Omron CX-Programmer project 新規ﾌﾟﾛｼﾞｪｸﾄ (CX-Programmer 9.73)

# PLC 受電PLC: CJ2M CPU34
I/O table (CPU CJ2M-CPU34): rack 0 slot 0 CJ1W-ID231; rack 0 slot 1 CJ1W-OD231; rack 0 slot 2 CJ1W-AD081; rack 0 slot 11 CJ2M-EIP21

## Global symbols (name address type ; comment)
0.00 BOOL  ; 自動運転
0.01 BOOL  ; ﾏｽﾀｰｽｲｯﾁ切
0.02 BOOL  ; ﾏｽﾀｰｽｲｯﾁ入
0.03 BOOL  ; CB0選択
0.04 BOOL  ; CB1選択
0.05 BOOL  ; CB2選択
0.06 BOOL  ; CB3選択
0.07 BOOL  ; CB4選択
0.08 BOOL  ; CB5選択
0.09 BOOL  ; CB6選択
0.10 BOOL  ; CB7選択
0.11 BOOL  ; CB8選択
2000 CHANNEL  ; ﾋﾟｰｸﾎｰﾙﾄﾞ機能
2001 CHANNEL  ; 受電電力
2002 CHANNEL  ; 1号機発電電力
2003 CHANNEL  ; 2号機発電電力
2004 CHANNEL  ; 負荷1電力
2005 CHANNEL  ; 負荷2電力
2006 CHANNEL  ; 負荷3電力
2009 CHANNEL  ; ｱﾗｰﾑﾌﾗｸﾞ/断線検知
2.00 BOOL  ; CB0(受電) ON
2.01 BOOL  ; CB1（G1） ON
2.02 BOOL  ; CB2(G2) ON
2.03 BOOL  ; CB3(L1) ON
2.04 BOOL  ; CB4(L2) ON
2.05 BOOL  ; CB5(L3) ON
2.06 BOOL  ; CB6(L1)ON
2.07 BOOL  ; CB7(L3)ON
2.08 BOOL  ; CB8(L3)ON
3.00 BOOL  ; CB0(受電)選択
3.01 BOOL  ; CB1(G1)選択
3.02 BOOL  ; CB2(G2)選択
3.03 BOOL  ; CB3(L1)選択
3.04 BOOL  ; CB4(L2)選択
3.05 BOOL  ; CB5(L3)選択
3.06 BOOL  ; CB6(L1)選択
3.07 BOOL  ; CB7(L3)選択
3.08 BOOL  ; CB8(L3)選択
D0 CHANNEL  ; 受電電力kW
D1 CHANNEL  ; 発電機G1出力kW
D2 CHANNEL  ; 発電機G2出力kW
D3 CHANNEL  ; 負荷L1電力kW
D4 CHANNEL  ; 負荷L2電力kW
D5 CHANNEL  ; 負荷L3電力kW
T0000 BOOL  ; CB1(G1)ON遅延
T0001 BOOL  ; CB2(G2)ON遅延
T0002 BOOL  ; CB1(G1)OFF
T0003 BOOL  ; CB2(G2)OFF遅延
W0.01 BOOL  ; CB1選択
W0.02 BOOL  ; CB2選択
W5.00 BOOL  ; 発電機運転0台
W5.01 BOOL  ; 発電機運転1台
W5.02 BOOL  ; 発電機運転2台
W5.03 BOOL  ; CB1(G1)OFF
W5.04 BOOL  ; CB2(G2)OFF

## Program 制御ﾌﾟﾛｸﾞﾗﾑ (cyclic task 0)

### Section 自動

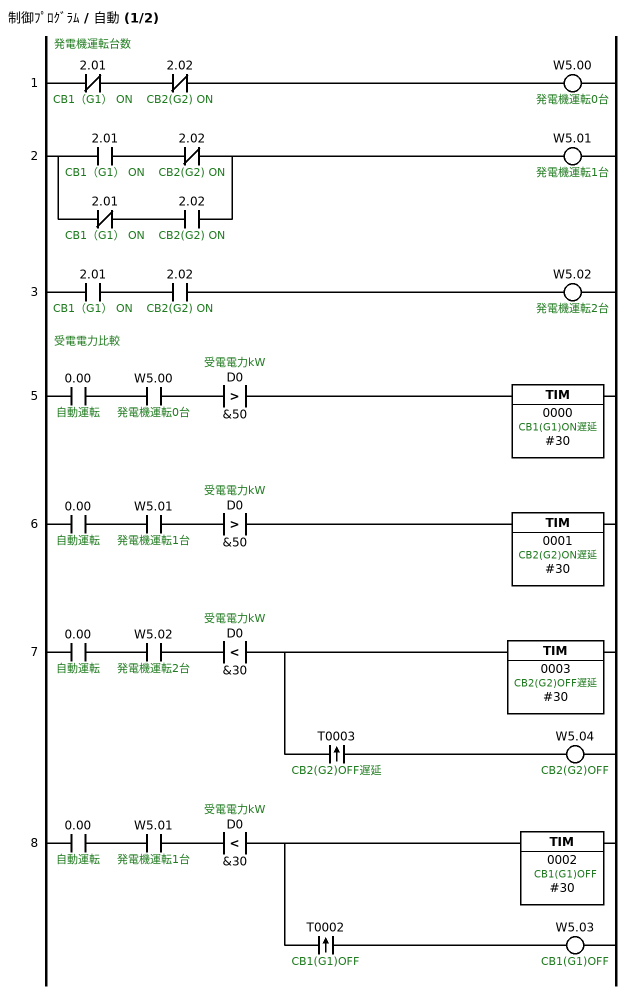
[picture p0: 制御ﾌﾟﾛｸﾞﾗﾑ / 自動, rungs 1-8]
; rung 1: 発電機運転台数
LDNOT 2.01  ; CB1（G1） ON
ANDNOT 2.02  ; CB2(G2) ON
OUT W5.00  ; 発電機運転0台
; rung 2
LD 2.01  ; CB1（G1） ON
ANDNOT 2.02  ; CB2(G2) ON
LDNOT 2.01  ; CB1（G1） ON
AND 2.02  ; CB2(G2) ON
ORLD
OUT W5.01  ; 発電機運転1台
; rung 3
LD 2.01  ; CB1（G1） ON
AND 2.02  ; CB2(G2) ON
OUT W5.02  ; 発電機運転2台
; rung 5: 受電電力比較
LD 0.00  ; 自動運転
AND W5.00  ; 発電機運転0台
AND>(320) D0 &50  ; 受電電力kW
TIM 0000 #30  ; CB1(G1)ON遅延
; rung 6
LD 0.00  ; 自動運転
AND W5.01  ; 発電機運転1台
AND>(320) D0 &50  ; 受電電力kW
TIM 0001 #30  ; CB2(G2)ON遅延
; rung 7
LD 0.00  ; 自動運転
AND W5.02  ; 発電機運転2台
AND<(310) D0 &30  ; 受電電力kW
TIM 0003 #30  ; CB2(G2)OFF遅延
@AND T0003  ; CB2(G2)OFF遅延
OUT W5.04  ; CB2(G2)OFF
; rung 8
LD 0.00  ; 自動運転
AND W5.01  ; 発電機運転1台
AND<(310) D0 &30  ; 受電電力kW
TIM 0002 #30  ; CB1(G1)OFF
@AND T0002  ; CB1(G1)OFF
OUT W5.03  ; CB1(G1)OFF

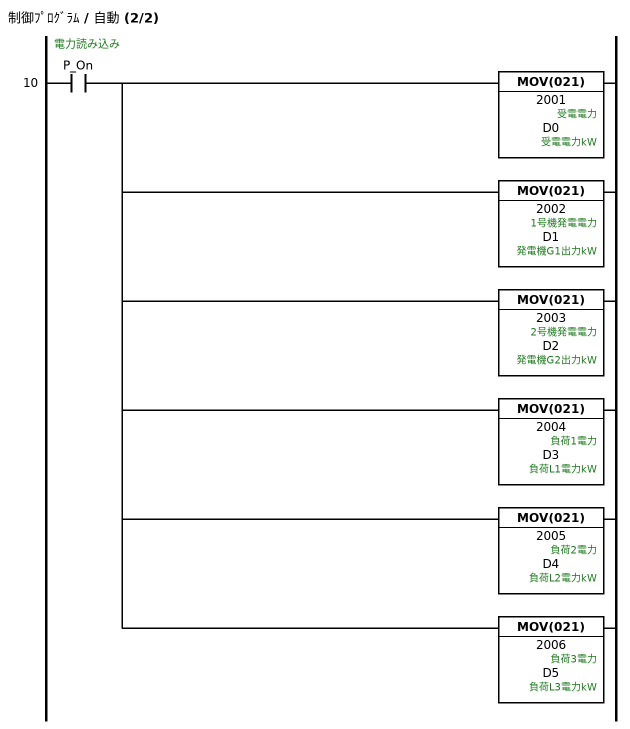
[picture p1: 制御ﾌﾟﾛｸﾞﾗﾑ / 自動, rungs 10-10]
; rung 10: 電力読み込み
LD P_On
MOV(021) 2001 D0  ; 受電電力, 受電電力kW
MOV(021) 2002 D1  ; 1号機発電電力, 発電機G1出力kW
MOV(021) 2003 D2  ; 2号機発電電力, 発電機G2出力kW
MOV(021) 2004 D3  ; 負荷1電力, 負荷L1電力kW
MOV(021) 2005 D4  ; 負荷2電力, 負荷L2電力kW
MOV(021) 2006 D5  ; 負荷3電力, 負荷L3電力kW

### Section 手動

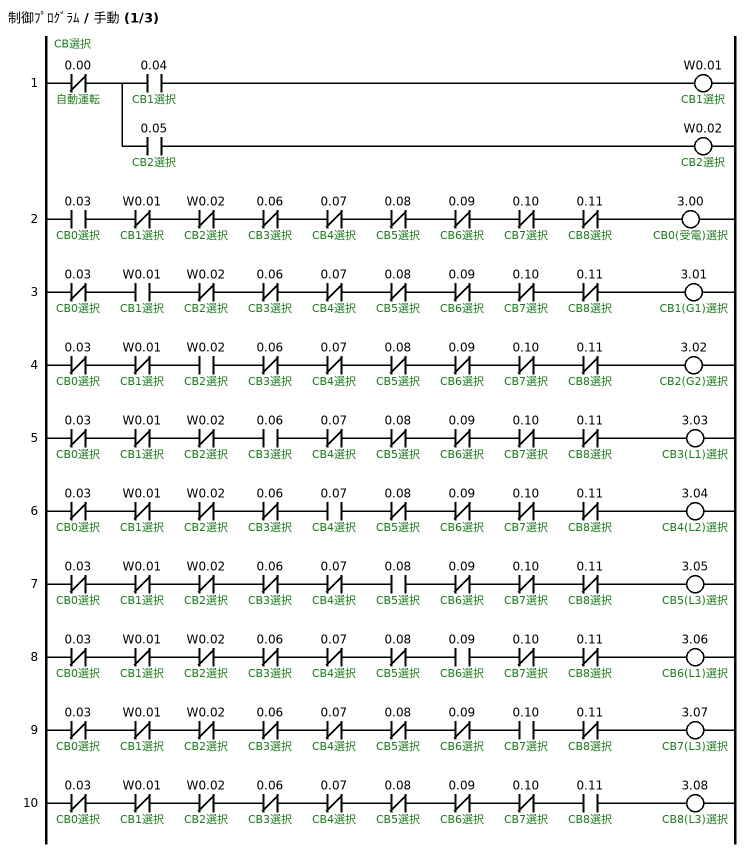
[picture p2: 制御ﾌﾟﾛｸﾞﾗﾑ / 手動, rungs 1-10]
; rung 1: CB選択
LDNOT 0.00  ; 自動運転
OUT TR0
AND 0.04  ; CB1選択
OUT W0.01  ; CB1選択
LD TR0
AND 0.05  ; CB2選択
OUT W0.02  ; CB2選択
; rung 2
LD 0.03  ; CB0選択
ANDNOT W0.01  ; CB1選択
ANDNOT W0.02  ; CB2選択
ANDNOT 0.06  ; CB3選択
ANDNOT 0.07  ; CB4選択
ANDNOT 0.08  ; CB5選択
ANDNOT 0.09  ; CB6選択
ANDNOT 0.10  ; CB7選択
ANDNOT 0.11  ; CB8選択
OUT 3.00  ; CB0(受電)選択
; rung 3
LDNOT 0.03  ; CB0選択
AND W0.01  ; CB1選択
ANDNOT W0.02  ; CB2選択
ANDNOT 0.06  ; CB3選択
ANDNOT 0.07  ; CB4選択
ANDNOT 0.08  ; CB5選択
ANDNOT 0.09  ; CB6選択
ANDNOT 0.10  ; CB7選択
ANDNOT 0.11  ; CB8選択
OUT 3.01  ; CB1(G1)選択
; rung 4
LDNOT 0.03  ; CB0選択
ANDNOT W0.01  ; CB1選択
AND W0.02  ; CB2選択
ANDNOT 0.06  ; CB3選択
ANDNOT 0.07  ; CB4選択
ANDNOT 0.08  ; CB5選択
ANDNOT 0.09  ; CB6選択
ANDNOT 0.10  ; CB7選択
ANDNOT 0.11  ; CB8選択
OUT 3.02  ; CB2(G2)選択
; rung 5
LDNOT 0.03  ; CB0選択
ANDNOT W0.01  ; CB1選択
ANDNOT W0.02  ; CB2選択
AND 0.06  ; CB3選択
ANDNOT 0.07  ; CB4選択
ANDNOT 0.08  ; CB5選択
ANDNOT 0.09  ; CB6選択
ANDNOT 0.10  ; CB7選択
ANDNOT 0.11  ; CB8選択
OUT 3.03  ; CB3(L1)選択
; rung 6
LDNOT 0.03  ; CB0選択
ANDNOT W0.01  ; CB1選択
ANDNOT W0.02  ; CB2選択
ANDNOT 0.06  ; CB3選択
AND 0.07  ; CB4選択
ANDNOT 0.08  ; CB5選択
ANDNOT 0.09  ; CB6選択
ANDNOT 0.10  ; CB7選択
ANDNOT 0.11  ; CB8選択
OUT 3.04  ; CB4(L2)選択
; rung 7
LDNOT 0.03  ; CB0選択
ANDNOT W0.01  ; CB1選択
ANDNOT W0.02  ; CB2選択
ANDNOT 0.06  ; CB3選択
ANDNOT 0.07  ; CB4選択
AND 0.08  ; CB5選択
ANDNOT 0.09  ; CB6選択
ANDNOT 0.10  ; CB7選択
ANDNOT 0.11  ; CB8選択
OUT 3.05  ; CB5(L3)選択
; rung 8
LDNOT 0.03  ; CB0選択
ANDNOT W0.01  ; CB1選択
ANDNOT W0.02  ; CB2選択
ANDNOT 0.06  ; CB3選択
ANDNOT 0.07  ; CB4選択
ANDNOT 0.08  ; CB5選択
AND 0.09  ; CB6選択
ANDNOT 0.10  ; CB7選択
ANDNOT 0.11  ; CB8選択
OUT 3.06  ; CB6(L1)選択
; rung 9
LDNOT 0.03  ; CB0選択
ANDNOT W0.01  ; CB1選択
ANDNOT W0.02  ; CB2選択
ANDNOT 0.06  ; CB3選択
ANDNOT 0.07  ; CB4選択
ANDNOT 0.08  ; CB5選択
ANDNOT 0.09  ; CB6選択
AND 0.10  ; CB7選択
ANDNOT 0.11  ; CB8選択
OUT 3.07  ; CB7(L3)選択
; rung 10
LDNOT 0.03  ; CB0選択
ANDNOT W0.01  ; CB1選択
ANDNOT W0.02  ; CB2選択
ANDNOT 0.06  ; CB3選択
ANDNOT 0.07  ; CB4選択
ANDNOT 0.08  ; CB5選択
ANDNOT 0.09  ; CB6選択
ANDNOT 0.10  ; CB7選択
AND 0.11  ; CB8選択
OUT 3.08  ; CB8(L3)選択

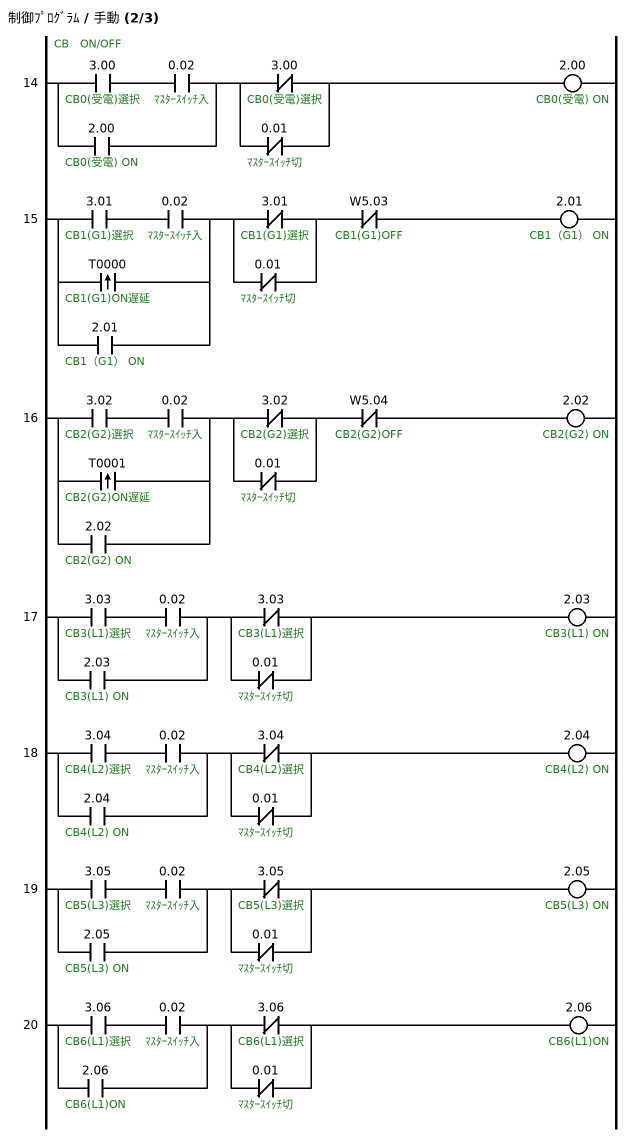
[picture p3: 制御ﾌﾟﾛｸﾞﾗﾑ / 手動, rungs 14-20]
; rung 14: CB　ON/OFF
LD 3.00  ; CB0(受電)選択
AND 0.02  ; ﾏｽﾀｰｽｲｯﾁ入
OR 2.00  ; CB0(受電) ON
LDNOT 3.00  ; CB0(受電)選択
ORNOT 0.01  ; ﾏｽﾀｰｽｲｯﾁ切
ANDLD
OUT 2.00  ; CB0(受電) ON
; rung 15
LD 3.01  ; CB1(G1)選択
AND 0.02  ; ﾏｽﾀｰｽｲｯﾁ入
@OR T0000  ; CB1(G1)ON遅延
OR 2.01  ; CB1（G1） ON
LDNOT 3.01  ; CB1(G1)選択
ORNOT 0.01  ; ﾏｽﾀｰｽｲｯﾁ切
ANDLD
ANDNOT W5.03  ; CB1(G1)OFF
OUT 2.01  ; CB1（G1） ON
; rung 16
LD 3.02  ; CB2(G2)選択
AND 0.02  ; ﾏｽﾀｰｽｲｯﾁ入
@OR T0001  ; CB2(G2)ON遅延
OR 2.02  ; CB2(G2) ON
LDNOT 3.02  ; CB2(G2)選択
ORNOT 0.01  ; ﾏｽﾀｰｽｲｯﾁ切
ANDLD
ANDNOT W5.04  ; CB2(G2)OFF
OUT 2.02  ; CB2(G2) ON
; rung 17
LD 3.03  ; CB3(L1)選択
AND 0.02  ; ﾏｽﾀｰｽｲｯﾁ入
OR 2.03  ; CB3(L1) ON
LDNOT 3.03  ; CB3(L1)選択
ORNOT 0.01  ; ﾏｽﾀｰｽｲｯﾁ切
ANDLD
OUT 2.03  ; CB3(L1) ON
; rung 18
LD 3.04  ; CB4(L2)選択
AND 0.02  ; ﾏｽﾀｰｽｲｯﾁ入
OR 2.04  ; CB4(L2) ON
LDNOT 3.04  ; CB4(L2)選択
ORNOT 0.01  ; ﾏｽﾀｰｽｲｯﾁ切
ANDLD
OUT 2.04  ; CB4(L2) ON
; rung 19
LD 3.05  ; CB5(L3)選択
AND 0.02  ; ﾏｽﾀｰｽｲｯﾁ入
OR 2.05  ; CB5(L3) ON
LDNOT 3.05  ; CB5(L3)選択
ORNOT 0.01  ; ﾏｽﾀｰｽｲｯﾁ切
ANDLD
OUT 2.05  ; CB5(L3) ON
; rung 20
LD 3.06  ; CB6(L1)選択
AND 0.02  ; ﾏｽﾀｰｽｲｯﾁ入
OR 2.06  ; CB6(L1)ON
LDNOT 3.06  ; CB6(L1)選択
ORNOT 0.01  ; ﾏｽﾀｰｽｲｯﾁ切
ANDLD
OUT 2.06  ; CB6(L1)ON

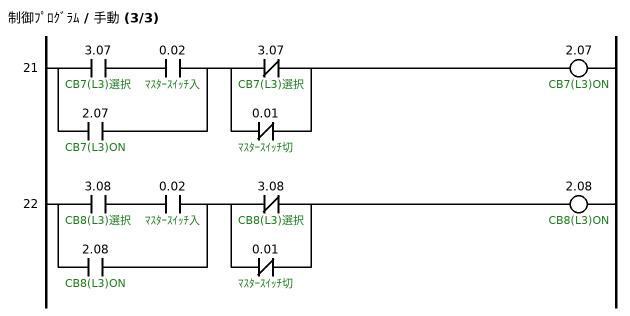
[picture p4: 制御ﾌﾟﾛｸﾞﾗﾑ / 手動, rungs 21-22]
; rung 21
LD 3.07  ; CB7(L3)選択
AND 0.02  ; ﾏｽﾀｰｽｲｯﾁ入
OR 2.07  ; CB7(L3)ON
LDNOT 3.07  ; CB7(L3)選択
ORNOT 0.01  ; ﾏｽﾀｰｽｲｯﾁ切
ANDLD
OUT 2.07  ; CB7(L3)ON
; rung 22
LD 3.08  ; CB8(L3)選択
AND 0.02  ; ﾏｽﾀｰｽｲｯﾁ入
OR 2.08  ; CB8(L3)ON
LDNOT 3.08  ; CB8(L3)選択
ORNOT 0.01  ; ﾏｽﾀｰｽｲｯﾁ切
ANDLD
OUT 2.08  ; CB8(L3)ON

### Section END
; rung 0
END(001)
